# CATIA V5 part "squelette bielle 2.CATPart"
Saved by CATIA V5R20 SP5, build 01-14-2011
Part number: squelette bielle 2
Bounding box of the stored display mesh (mm): x 1350.429 to 2851.425, y -10000 to 10000, z 7536.862 to 11883.673
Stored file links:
  M:\EU_thinkMotion\IAO_2010\iao\IAO_MMS_Groupe1\Problemes\gduval\Gduval\train d'aterrissage squelette + piece kinematic\squelette bielle 2.CATPart
  M:\EU_thinkMotion\IAO_2010\iao\IAO_MMS_Groupe1\Problemes\gduval\Gduval\train d'aterrissage squelette + piece kinematic\train d'aterrissage.CATProduct
  M:\EU_thinkMotion\IAO_2010\iao\IAO_MMS_Groupe1\Problemes\gduval\Gduval\train d'aterrissage squelette + piece kinematic\squelette de base.CATPart
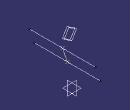
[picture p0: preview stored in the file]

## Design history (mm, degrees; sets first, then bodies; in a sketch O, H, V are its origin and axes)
External parameters (linked from other documents)
  `External.epaisseur bielle` = 500 mm
Set1
  Point1: linked copy from another document
  Point2: linked copy from another document
  Plane1: linked copy from another document
Body1 (main body)
  Line1: type PtPt, FirstPoint Point1, SecondPoint Point2
  Line2: type Normal, RefPoint Point1, RefSkin Plane1, Start 10000, End -10000
  Plane2: type Offset, RefPlane Plane1, Offset 500 {= `External.epaisseur bielle`}
  Line3: type Normal, RefPoint Point2, RefSkin Plane1, Start 10000, End -10000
